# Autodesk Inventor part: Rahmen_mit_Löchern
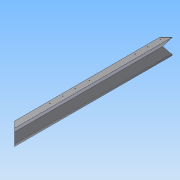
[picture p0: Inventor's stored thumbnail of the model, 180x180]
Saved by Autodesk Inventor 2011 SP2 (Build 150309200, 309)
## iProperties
Created: 2009-11
Part Number: Rahmen_mit_Löchern
Document SubType Name: Modeling
Designer: gkramp
Density: 1 g/cm^3
Author: gkramp
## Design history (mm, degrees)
derived "Masterbaugruppe.iam"
sketch "Skizze1_2"
  geometry: L1 (-40, 100)-(0, 100) reference; L2 (0, 100)-(-30, 50) reference; L3 (-30, 50)-(-3.477, 10) reference; L4 (-3.477, 10)-(0, 10) reference; L5 (0, 10)-(0, 0) reference; L6 (0, 0)-(-40, 0) reference; L7 (0, 37.459)-(0, -9.286) reference; L8 (-3.707, 0)-(22.509, 0) reference; L9 (-40, 98.5)-(-2.649, 98.5) reference; L10 (-2.649, 98.5)-(-31.773, 49.96) reference; L11 (-31.773, 49.96)-(-4.283, 8.5) reference; L12 (-4.283, 8.5)-(-1.5, 8.5) reference; L13 (-1.5, 8.5)-(-1.5, 1.5) reference; L14 (-1.5, 1.5)-(-40, 1.5) reference; L15 (-40, 100)-(-40, 98.5) reference; L16 (-40, 1.5)-(-40, 0) reference
extrude "Extrusion1" new body sketch "Skizze1_2" stored distance "d10" = 10; taper "d11" = 0 deg
sketch "Skizze5"
  geometry: 8 further points
hole "Bohrung1" sketch "Skizze5" at (-25, 250), (-25, 330), (-25, 410), (-25, 500), (-25, 790), (-25, 870), (-25, 950) diameter "d16" = 4.5; stored, may be unused: countersink angle "d20" = 90 deg, drill point angle "d22" = 118 deg; dims "d17" = 6, "d18" = 4, "d19" = 2, "d21" = 8
node "Volumenkörper1"
node "Volumenkörpern"
node "Oberflächenkörpern"
node "BaugruppenMasterskizze.ipt:1"
node "Profilskizze.ipt:1"
node "Profilskizze.ipt:2"
sketch "Skizze1"
  geometry: L1 (-450, 500)-(-305.18, 355.18) reference; L2 (450, 500)-(305.18, 355.18) reference; L3 (-450, -500)-(-305.18, -355.18) reference; L4 (-305.18, -355.18)-(305.18, -355.18) reference; L5 (305.18, -355.18)-(450, -500) reference; L6 (305.18, 355.18)-(305.18, -355.18) reference; L7 (305.18, 355.18)-(-305.18, 355.18) reference; L8 (-305.18, 355.18)-(-305.18, -355.18) reference; L9 (-450, -500)-(450, -500) reference; L10 (450, -500)-(450, 500) reference; L11 (450, 500)-(-450, 500) reference; L12 (-450, 500)-(-450, -500) reference; L13 (0, 23.685)-(0, -25.883) reference; L14 (-18.992, 0)-(22.934, 0) reference; 9 further points
  constraints: 1 other
workplane "Arbeitsebene1"
workplane "Arbeitsebene2"
workplane "Arbeitsebene3"
workplane "Arbeitsebene4"
sketch "Skizze1_1"
  geometry: L1 (-40, 100)-(0, 100) reference; L2 (0, 100)-(-30, 50) reference; L3 (-30, 50)-(-3.477, 10) reference; L4 (-3.477, 10)-(0, 10) reference; L5 (0, 10)-(0, 0) reference; L6 (0, 0)-(-40, 0) reference; L7 (0, 37.459)-(0, -9.286) reference; L8 (-3.707, 0)-(22.509, 0) reference; L9 (-40, 98.5)-(-2.649, 98.5) reference; L10 (-2.649, 98.5)-(-31.773, 49.96) reference; L11 (-31.773, 49.96)-(-4.283, 8.5) reference; L12 (-4.283, 8.5)-(-1.5, 8.5) reference; L13 (-1.5, 8.5)-(-1.5, 1.5) reference; L14 (-1.5, 1.5)-(-40, 1.5) reference; L15 (-40, 100)-(-40, 98.5) reference; L16 (-40, 1.5)-(-40, 0) reference
other parameters: "d2" = 0, "d4" = 0, "d6" = 0, "d8" = 0, "d12" = 0, "d10_1" = 144.82031, "d12_1" = 90 deg, "d13" = 90 deg, "d14" = 90 deg, "d15" = 90 deg, "d4_2" = 3.4774, "d7_1" = 1.5, "d4_3" = 3.4774, "d7_2" = 1.5
